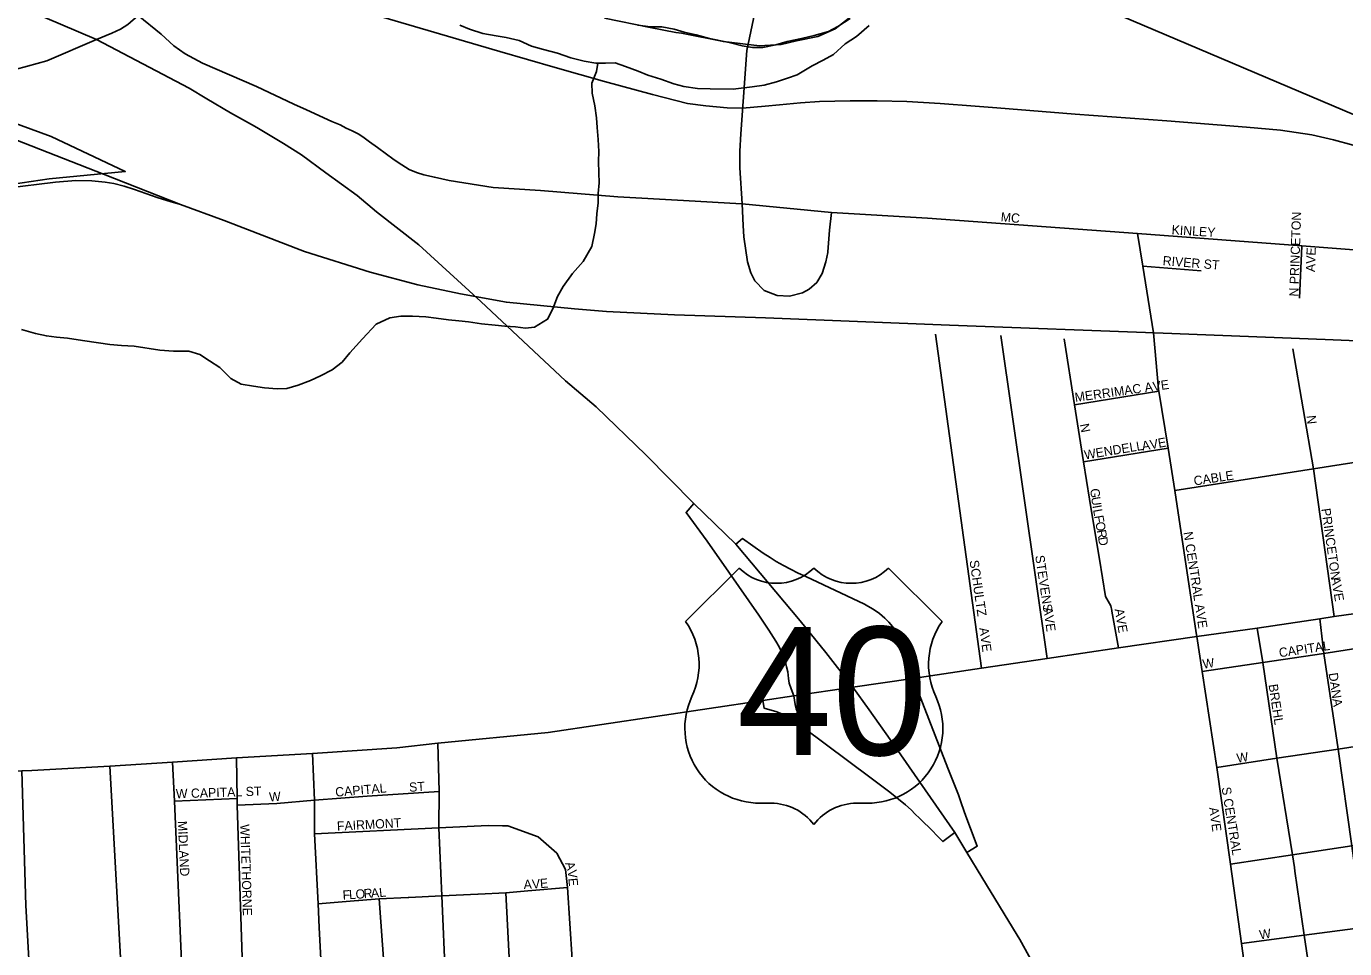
# Model space of a CAD drawing. Extents: x 0 to 34, y -6.2 to 22.
# Drawn here: x 3.469 to 4.825, y 17.432 to 18.38 of the extents above; entities that cross this region are included whole.
import ezdxf

# ---------------------------------------------------------------- set-up
doc = ezdxf.new("R2010")
doc.units = 0
for name, color, linetype in [('GM_X_City_Street', 7, 'Continuous'), ('GM_X_City_Street_Text', 7, 'Continuous'), ('GM_X_Corporation', 7, 'Continuous'), ('GM_X_Interchange_Ramps', 7, 'Continuous'), ('GM_X_Interstate_Route', 7, 'Continuous'), ('GM_X_Major_River', 7, 'Continuous'), ('GM_X_Minor_River', 7, 'Continuous'), ('GM_X_Rail_Line', 7, 'Continuous'), ('GM_X_Section', 7, 'Continuous'), ('GM_X_US_Route', 7, 'Continuous'), ('GM_X_US_Shield', 7, 'Continuous')]:
    doc.layers.add(name, color=color, linetype=linetype)

msp = doc.modelspace()

# ---------------------------------------------------------------- linework, layer by layer
at = {"layer": 'GM_X_City_Street'}
for points in [[(4.2061, 18.1755), (4.2049, 18.1978), (4.2028, 18.2345), (4.2028, 18.2519), (4.2036, 18.2695), (4.2061, 18.303), (4.2099, 18.3554), (4.2236, 18.4209)], [(3.354, 18.3169), (3.357, 18.3181), (3.3663, 18.322), (3.3881, 18.3285), (3.3978, 18.3304), (3.415, 18.3325), (3.4446, 18.3339), (3.4576, 18.3358), (3.4701, 18.3392), (3.4899, 18.3448), (3.5412, 18.3666), (3.5569, 18.373), (3.5657, 18.3772), (3.5734, 18.3821), (3.5839, 18.3913)], [(4.1446, 18.2012), (4.0771, 18.205), (3.9976, 18.2114), (3.949, 18.2146), (3.9038, 18.2216), (3.8886, 18.2249), (3.8777, 18.2273), (3.8702, 18.2297), (3.8627, 18.2328), (3.8512, 18.24), (3.8457, 18.2439), (3.8392, 18.2488), (3.83, 18.2556), (3.8219, 18.2614), (3.8163, 18.2656), (3.8108, 18.2691), (3.8041, 18.2728), (3.798, 18.2756), (3.7916, 18.2788), (3.7831, 18.2824), (3.7569, 18.2944), (3.7442, 18.3002), (3.7056, 18.3184), (3.65, 18.3421), (3.6324, 18.352), (3.6207, 18.3601), (3.6075, 18.3721), (3.5839, 18.3913)], [(4.2043, 18.1978), (4.1446, 18.2012)], [(4.6114, 18.1673), (4.3955, 18.183), (4.297, 18.1886), (4.2049, 18.1978), (4.2043, 18.1978)], [(4.297, 18.1886), (4.295, 18.1706), (4.2931, 18.1484), (4.293, 18.1476)], [(4.293, 18.1476), (4.291, 18.1379), (4.2873, 18.1259), (4.2819, 18.1168), (4.2739, 18.1099), (4.267, 18.1063), (4.2536, 18.1026), (4.2409, 18.1034), (4.2278, 18.1085), (4.218, 18.1186), (4.214, 18.1266), (4.2107, 18.1379), (4.2067, 18.1637), (4.2061, 18.1755)], [(5.0508, 18.1356), (4.9707, 18.141), (4.8473, 18.1492), (4.7807, 18.1543), (4.6114, 18.1673)], [(4.6719, 17.7566), (4.65, 17.903), (4.643, 17.9465), (4.6336, 18.0049), (4.6332, 18.0072), (4.6279, 18.065), (4.6169, 18.1336), (4.6114, 18.1673)], [(4.7782, 18.1007), (4.7807, 18.1543)], [(4.6169, 18.1336), (4.6769, 18.1289)], [(4.451, 17.7202), (4.4038, 18.0638)], [(4.5186, 17.7302), (4.4712, 18.0622)], [(4.5623, 17.8941), (4.5562, 17.9324), (4.5469, 17.9911), (4.5362, 18.0587)], [(4.8138, 17.7733), (4.7925, 17.9253), (4.7712, 18.0484)], [(4.5469, 17.9911), (4.6336, 18.0049)], [(4.65, 17.903), (4.7925, 17.9253), (4.8603, 17.9359), (4.9313, 17.9469), (4.9831, 17.955)], [(4.5562, 17.9324), (4.643, 17.9465)], [(4.5852, 17.7796), (4.5843, 17.7845), (4.5785, 17.7938), (4.5726, 17.8323), (4.563, 17.8896), (4.5623, 17.8941)], [(4.5919, 17.741), (4.5853, 17.7789), (4.5852, 17.7796)], [(4.7734, 17.5116), (4.7729, 17.5155), (4.771, 17.5283), (4.755, 17.6276), (4.7405, 17.726), (4.7347, 17.7615)], [(4.7405, 17.726), (4.8033, 17.7355), (4.8626, 17.7445), (4.9332, 17.7556), (5.0048, 17.7658)], [(4.8832, 17.1912), (4.8743, 17.2504), (4.87, 17.2759), (4.8718, 17.281), (4.8638, 17.3316), (4.8432, 17.4538), (4.8319, 17.5375), (4.818, 17.6371), (4.8033, 17.7355), (4.7989, 17.7709)], [(4.7071, 17.5186), (4.6931, 17.6183), (4.6782, 17.7168), (4.6725, 17.7528), (4.6719, 17.7566)], [(4.6782, 17.7168), (4.7405, 17.726)], [(4.6931, 17.6183), (4.755, 17.6276), (4.818, 17.6371), (4.8773, 17.6461), (4.9579, 17.6581), (5.0194, 17.6672), (5.0489, 17.6714)], [(3.9039, 17.3122), (3.8963, 17.4862), (3.8933, 17.5562), (3.8934, 17.5933), (3.8922, 17.643)], [(3.6529, 16.9916), (3.642, 17.14), (3.6314, 17.3561), (3.6214, 17.5837), (3.6194, 17.6236)], [(3.7167, 17.0066), (3.7063, 17.1432), (3.6931, 17.3603), (3.6859, 17.5795), (3.6856, 17.5864), (3.685, 17.6282)], [(3.7947, 17.0334), (3.7927, 17.0589), (3.7792, 17.2778), (3.7702, 17.4538), (3.769, 17.4781), (3.7653, 17.55), (3.7653, 17.5845), (3.7633, 17.6324)], [(3.5038, 16.9353), (3.5023, 16.9435), (3.5002, 16.955), (3.4976, 16.9872), (3.494, 17.0525), (3.4904, 17.0753), (3.4856, 17.1654), (3.4855, 17.1663), (3.4847, 17.1818), (3.4743, 17.3716), (3.4685, 17.4762), (3.4642, 17.6146)], [(3.5896, 16.9856), (3.5877, 17.0084), (3.582, 17.0834), (3.579, 17.137), (3.5767, 17.1883), (3.5694, 17.352), (3.5682, 17.3797), (3.5549, 17.6194)], [(3.6214, 17.5837), (3.6856, 17.5864)], [(3.6859, 17.5795), (3.7265, 17.5812), (3.7653, 17.5845)], [(3.7653, 17.5845), (3.8194, 17.5886), (3.8934, 17.5933)], [(3.7653, 17.55), (3.8933, 17.5562), (3.9437, 17.5586), (3.9587, 17.5582)], [(3.9587, 17.5582), (3.9591, 17.5582), (3.9642, 17.5581), (3.9954, 17.547), (4.0144, 17.5302), (4.0235, 17.5133), (4.0253, 17.4946)], [(4.8139, 17.2406), (4.813, 17.2463), (4.8098, 17.2662), (4.783, 17.4459), (4.7734, 17.5116)], [(3.8623, 17.4845), (3.8963, 17.4862), (3.9334, 17.488), (3.9337, 17.488)], [(3.9337, 17.488), (3.9621, 17.4893), (3.9846, 17.4912), (3.9846, 17.4912)], [(3.9911, 17.072), (3.9704, 17.3297), (3.9621, 17.4893)], [(3.9846, 17.4912), (4.0253, 17.4946)], [(4.035, 17.3455), (4.0349, 17.3466), (4.0253, 17.4946)], [(3.769, 17.4781), (3.8101, 17.4813), (3.8108, 17.4814)], [(3.8108, 17.4814), (3.8317, 17.483), (3.8615, 17.4845), (3.8623, 17.4845)], [(3.845, 17.2987), (3.8317, 17.483)], [(4.7185, 17.4373), (4.783, 17.4459), (4.8432, 17.4538), (4.9032, 17.4617), (4.9884, 17.473), (5.0459, 17.4806), (5.0754, 17.4845)]]:
    msp.add_lwpolyline(points, dxfattribs=at)
at = {"layer": 'GM_X_Corporation'}
msp.add_lwpolyline([(3.4223, 18.2933), (3.4945, 18.2667), (3.5707, 18.2308), (3.4925, 18.2234), (3.4367, 18.2152)], dxfattribs=at)
at = {"layer": 'GM_X_Interchange_Ramps'}
for points in [[(4.1555, 17.8896), (4.1473, 17.8803), (4.1689, 17.8507), (4.1912, 17.819), (4.2222, 17.7748), (4.2325, 17.7595), (4.2396, 17.7481), (4.2431, 17.7422), (4.2455, 17.7372), (4.2479, 17.7314), (4.2495, 17.7266), (4.2508, 17.7218), (4.2519, 17.7164), (4.2526, 17.7095), (4.2533, 17.7047), (4.2556, 17.6991), (4.2583, 17.6917)], [(4.3806, 17.7098), (4.3776, 17.7187), (4.3761, 17.7284), (4.3752, 17.7324), (4.3736, 17.7376), (4.3717, 17.7427), (4.3696, 17.7475), (4.3666, 17.7529), (4.3635, 17.7579), (4.3597, 17.7631), (4.3559, 17.7674), (4.3516, 17.7717), (4.3463, 17.7763), (4.3398, 17.781), (4.3344, 17.7841), (4.3308, 17.786), (4.2704, 17.8145), (4.2626, 17.818), (4.2546, 17.8219), (4.2474, 17.8258), (4.24, 17.8301), (4.2337, 17.8339), (4.2265, 17.8386), (4.2053, 17.8535), (4.1985, 17.8479)], [(4.4361, 17.5308), (4.4468, 17.5371), (4.44, 17.5554), (4.4352, 17.5682), (4.4307, 17.5808), (4.4274, 17.5901), (4.4166, 17.6175), (4.3838, 17.7013), (4.3806, 17.7098)], [(4.2583, 17.6917), (4.2596, 17.6828), (4.2607, 17.6783), (4.2625, 17.6738), (4.2645, 17.6699), (4.2665, 17.6669), (4.2698, 17.6628), (4.2674, 17.6596)], [(4.2264, 17.687), (4.2276, 17.6792), (4.2408, 17.6753), (4.2464, 17.6731), (4.2513, 17.6708), (4.2569, 17.6675), (4.2619, 17.664), (4.2674, 17.6596), (4.3377, 17.6072), (4.3568, 17.5927), (4.373, 17.5799), (4.3787, 17.5745), (4.3831, 17.5703), (4.3873, 17.5662), (4.3922, 17.5614), (4.3969, 17.5568), (4.4011, 17.5526), (4.405, 17.5486), (4.4115, 17.542), (4.4237, 17.5512)]]:
    msp.add_lwpolyline(points, dxfattribs=at)
at = {"layer": 'GM_X_Interstate_Route'}
for points in [[(4.3418, 18.4877), (4.3545, 18.4838), (4.4533, 18.4494), (4.4812, 18.4384), (4.5209, 18.4223), (4.5477, 18.4108), (4.571, 18.4007), (4.8701, 18.274), (4.9358, 18.2459), (4.9591, 18.2362), (4.9768, 18.2297), (5.0011, 18.2219), (5.0179, 18.2177), (5.0369, 18.2146), (5.0555, 18.2123), (5.0721, 18.2113), (5.0956, 18.2113), (5.1163, 18.2131), (5.13, 18.2148), (5.1436, 18.2173), (5.1588, 18.2209), (5.1693, 18.2235), (5.1842, 18.2285)], [(3.4695, 18.3971), (3.5412, 18.3666), (3.6364, 18.3165), (3.6546, 18.3056)], [(3.6546, 18.3056), (3.6788, 18.2912), (3.7005, 18.2793), (3.7061, 18.276)], [(3.7061, 18.276), (3.7335, 18.2596), (3.7519, 18.2481), (3.7771, 18.2296), (3.8091, 18.2063), (3.8292, 18.1893), (3.8724, 18.1554), (3.9364, 18.0973), (4.0235, 18.0157), (4.055, 17.989), (4.1061, 17.9397), (4.1555, 17.8896), (4.1985, 17.8479), (4.2647, 17.7691), (4.2912, 17.7365), (4.3189, 17.7008)], [(4.3189, 17.7008), (4.3357, 17.6773)], [(4.3357, 17.6773), (4.3572, 17.647), (4.4237, 17.5512), (4.4361, 17.5308), (4.4516, 17.5053)], [(4.4516, 17.5053), (4.4877, 17.4458)], [(4.4877, 17.4458), (4.4905, 17.4412), (4.582, 17.2751), (4.5996, 17.2443), (4.6144, 17.2203)]]:
    msp.add_lwpolyline(points, dxfattribs=at)
at = {"layer": 'GM_X_Major_River'}
for points in [[(4.3162, 18.3883), (4.3033, 18.38), (4.2938, 18.3747), (4.279, 18.3706), (4.2661, 18.3677), (4.2513, 18.3644), (4.2396, 18.361), (4.2263, 18.3584), (4.2157, 18.3585), (4.2051, 18.3601), (4.1918, 18.3636), (4.1714, 18.3675), (4.1578, 18.3714), (4.1453, 18.3741), (4.1351, 18.3772), (4.1226, 18.3795), (4.1109, 18.3796), (4.0976, 18.3812)], [(3.9146, 18.3812), (3.9245, 18.3773), (3.9384, 18.3727), (3.9521, 18.3703), (3.9623, 18.3687), (3.9759, 18.3656), (3.9884, 18.3599), (4.0009, 18.3564), (4.0152, 18.3525), (4.0288, 18.3479), (4.0425, 18.3444), (4.0546, 18.3424), (4.0644, 18.3423), (4.0743, 18.3426), (4.0852, 18.3388), (4.0981, 18.3342), (4.1079, 18.3299), (4.1215, 18.3257), (4.1348, 18.321), (4.145, 18.3183), (4.159, 18.3163), (4.1722, 18.3159), (4.1957, 18.3157), (4.2154, 18.3179), (4.2276, 18.3197), (4.2405, 18.3231), (4.2515, 18.3268), (4.2617, 18.3301), (4.2769, 18.3395), (4.2883, 18.3455), (4.299, 18.3512), (4.3108, 18.3621), (4.3226, 18.3696), (4.3355, 18.3809)]]:
    msp.add_lwpolyline(points, dxfattribs=at)
at = {"layer": 'GM_X_Minor_River'}
msp.add_lwpolyline([(4.0566, 18.3424), (4.0554, 18.3338), (4.0503, 18.3217), (4.0509, 18.3115), (4.0534, 18.2985), (4.0551, 18.286), (4.0561, 18.2761), (4.0571, 18.2639), (4.0577, 18.2514), (4.0572, 18.2412), (4.0578, 18.2294), (4.058, 18.2191), (4.0571, 18.2081), (4.057, 18.1986), (4.0557, 18.1873), (4.0548, 18.177), (4.0531, 18.1672), (4.0503, 18.1539), (4.0417, 18.1385), (4.0306, 18.1261), (4.0209, 18.1126), (4.0151, 18.1024), (4.0104, 18.0896), (4.0049, 18.079), (3.9916, 18.0708), (3.9821, 18.0698), (3.9718, 18.0711), (3.9609, 18.072), (3.951, 18.0729), (3.937, 18.0742), (3.9238, 18.0763), (3.9136, 18.0772), (3.903, 18.0785), (3.8905, 18.0802), (3.8799, 18.0815), (3.8659, 18.082), (3.8541, 18.0822), (3.8427, 18.0805), (3.8286, 18.0738), (3.8148, 18.0588), (3.8017, 18.0446), (3.7936, 18.0348), (3.7833, 18.027), (3.7714, 18.0207), (3.7611, 18.0159), (3.7486, 18.0111), (3.7368, 18.0079), (3.7269, 18.0073), (3.7137, 18.0086), (3.7027, 18.0102), (3.6898, 18.0123), (3.6793, 18.0182), (3.6681, 18.0293), (3.6572, 18.0363), (3.6474, 18.0429), (3.6361, 18.0461), (3.6202, 18.0463), (3.6062, 18.0473), (3.5797, 18.0514), (3.5668, 18.052), (3.5547, 18.0529), (3.543, 18.0546), (3.5267, 18.0571), (3.5112, 18.0596), (3.4999, 18.0605), (3.4896, 18.0618), (3.4783, 18.0642), (3.464, 18.0686)], dxfattribs=at)
at = {"layer": 'GM_X_Rail_Line'}
for points in [[(3.8224, 18.3932), (3.9335, 18.3607), (3.9558, 18.3541), (4.0127, 18.3379), (4.0635, 18.3234), (4.1129, 18.3099), (4.1487, 18.3009), (4.1676, 18.2983), (4.1897, 18.2963), (4.2054, 18.2961), (4.2286, 18.2981)], [(2.2755, 18.3366), (2.399, 18.3449), (2.4759, 18.3502), (2.5318, 18.3539), (2.5883, 18.3579), (2.6939, 18.365), (2.8339, 18.3746), (2.8626, 18.3756), (2.9558, 18.3774), (3.0038, 18.3761), (3.0567, 18.3729), (3.1054, 18.3674), (3.1208, 18.3653), (3.1653, 18.3574), (3.1923, 18.3522), (3.2369, 18.3415), (3.279, 18.3296), (3.3073, 18.3207), (3.3671, 18.2986), (3.458, 18.2633), (3.5483, 18.2281)], [(4.2286, 18.2981), (4.2436, 18.2993), (4.265, 18.3016), (4.2846, 18.3027), (4.3162, 18.3035), (4.3437, 18.3037), (4.3745, 18.3028), (4.4087, 18.3007), (4.4447, 18.298), (4.4668, 18.2965), (4.5473, 18.29), (4.6418, 18.2829), (4.7237, 18.2765), (4.7586, 18.2733), (4.7907, 18.2686), (4.8131, 18.2633), (4.8334, 18.2579), (4.8511, 18.2521), (4.9336, 18.2204), (4.9803, 18.2024), (5.0081, 18.1943)], [(3.4147, 18.2097), (3.4988, 18.2198), (3.5198, 18.2216), (3.5364, 18.2213), (3.55, 18.22), (3.5588, 18.2184), (3.5695, 18.2158), (3.5801, 18.2125), (3.6034, 18.2042), (3.6178, 18.1997), (3.6274, 18.197)], [(3.5483, 18.2281), (3.6274, 18.197)], [(3.6274, 18.197), (3.6725, 18.1806), (3.7549, 18.1486), (3.8224, 18.1273), (3.8715, 18.1143), (3.9153, 18.1052), (3.9626, 18.0965), (4.0328, 18.0896), (4.0656, 18.0871), (4.1355, 18.0835), (4.2291, 18.0803), (4.4181, 18.073), (4.6379, 18.0646), (4.8046, 18.0581), (4.9693, 18.0513), (5.0439, 18.0491)]]:
    msp.add_lwpolyline(points, dxfattribs=at)
at = {"layer": 'GM_X_Section'}
msp.add_lwpolyline([(4.319, 18.3917), (4.3007, 18.3774), (4.2828, 18.3696), (4.2608, 18.3652), (4.2453, 18.3615), (4.2229, 18.3601), (4.1858, 18.3645), (4.1427, 18.3731), (4.137, 18.3739), (4.1105, 18.379), (4.0636, 18.3884)], dxfattribs=at)
at = {"layer": 'GM_X_US_Route'}
for points in [[(4.3806, 17.7098), (4.451, 17.7202), (4.5186, 17.7302), (4.5919, 17.741), (4.6725, 17.7528), (4.7347, 17.7615), (4.7989, 17.7709), (4.8138, 17.7733), (4.8583, 17.7796), (4.8845, 17.7839), (4.9279, 17.7904), (4.9528, 17.794), (4.9999, 17.8014), (5.0071, 17.8027), (5.0833, 17.8136), (5.1436, 17.8226), (5.1732, 17.8269)], [(4.3189, 17.7008), (4.3806, 17.7098)], [(4.2264, 17.687), (4.2264, 17.687), (4.2583, 17.6917), (4.3189, 17.7008)], [(3.4746, 17.6152), (3.5549, 17.6194), (3.6194, 17.6236), (3.685, 17.6282), (3.7633, 17.6324), (3.8498, 17.6382), (3.8922, 17.643), (4.0054, 17.654), (4.2264, 17.687)], [(2.7722, 17.5767), (2.835, 17.5781), (2.8913, 17.5814), (2.8978, 17.5817), (2.9479, 17.586), (2.9633, 17.5869), (3.0204, 17.5901), (3.0294, 17.5906), (3.0594, 17.5911), (3.0843, 17.5926), (3.1, 17.5935), (3.1552, 17.598), (3.1748, 17.5984), (3.2207, 17.6008), (3.2401, 17.602), (3.2786, 17.6048), (3.3066, 17.6072), (3.3458, 17.608), (3.36, 17.6082), (3.4047, 17.6118), (3.4151, 17.6124), (3.4642, 17.6146), (3.4746, 17.6152)], [(4.7071, 17.5186), (4.771, 17.5283), (4.8319, 17.5375), (4.8908, 17.5464), (4.9758, 17.5594), (5.0334, 17.5681), (5.1152, 17.5805)], [(4.7722, 17.089), (4.7612, 17.1636), (4.7485, 17.2517), (4.7342, 17.3247), (4.7258, 17.3847), (4.7185, 17.4373), (4.7071, 17.5186)]]:
    msp.add_lwpolyline(points, dxfattribs=at)
at = {"layer": 'GM_X_US_Shield'}
for p, q in [((4.2018, 17.8232), (4.1469, 17.7682)), ((4.4106, 17.7682), (4.3556, 17.8232)), ((4.2238, 17.5815), (4.2348, 17.5815)), ((4.3227, 17.5815), (4.3337, 17.5815))]:
    msp.add_line(p, q, dxfattribs=at)
for centre, radius, start, end in [((4.2403, 17.8624), 0.0549, 225.573, 314.427), ((4.3172, 17.8624), 0.0549, 225.573, 314.427), ((4.0839, 17.7241), 0.0769, 334.5471, 35.0009), ((4.4736, 17.7241), 0.0769, 144.9991, 205.4529), ((4.223, 17.6584), 0.0769, 154.8319, 270.6383), ((4.3345, 17.6584), 0.0769, 269.3617, 25.1681), ((4.2348, 17.5265), 0.0549, 36.8699, 90), ((4.3227, 17.5265), 0.0549, 90, 143.1301)]:
    msp.add_arc(centre, radius, start, end, dxfattribs=at)

# ---------------------------------------------------------------- texts
at = {"layer": 'GM_X_City_Street_Text'}
for s, rotation, p in [('MC', 354.8083, (4.4706, 18.1797)), ('N PRINCETON', 88.0895, (4.777, 18.1022)), ('KINLEY', 356.3071, (4.6464, 18.1664)), ('AVE', 88.0186, (4.7941, 18.1274)), ('RIVER ST', 355.3132, (4.6372, 18.1347)), ('MERRIMAC AVE', 7.9796, (4.5477, 17.9939)), ('N', 275.7084, (4.7855, 17.9798)), ('N', 281.3057, (4.5522, 17.9708)), ('WENDELL', 9.4634, (4.5576, 17.9347)), ('AVE', 9.7774, (4.6168, 17.9439)), ('CABLE', 8.6529, (4.6701, 17.908)), ('G', 274.8145, (4.563, 17.9047)), ('U', 278.4316, (4.5638, 17.8958)), ('I', 280.0994, (4.5651, 17.8872)), ('L', 280.1465, (4.5658, 17.8831)), ('PRINCETON', 278.1285, (4.8005, 17.884)), ('F', 280.1714, (4.567, 17.8766)), ('O', 280.1524, (4.5682, 17.87)), ('R', 280.1568, (4.5696, 17.8618)), ('D', 280.1537, (4.5709, 17.8544)), ('N CENTRAL AVE', 278.8659, (4.6588, 17.8599)), ('SCHULTZ', 278.2584, (4.4388, 17.8307)), ('STEVENS', 278.5295, (4.5063, 17.8357)), ('AVE', 279.7847, (4.8105, 17.8133)), ('AVE', 277.8566, (4.5147, 17.7824)), ('AVE', 279.7834, (4.588, 17.7808)), ('AVE', 277.8566, (4.4488, 17.7615)), ('CAPITAL', 8.3649, (4.7577, 17.7314)), ('W', 8.7411, (4.6793, 17.7197)), ('DANA', 278.5313, (4.808, 17.7149)), ('BREHL', 278.653, (4.7463, 17.7032)), ('W', 8.7411, (4.7143, 17.623)), ('W CAPITAL ST', 1.8078, (3.6229, 17.5864)), ('CAPITAL', 4.8438, (3.787, 17.5881)), ('ST', 3.5746, (3.8628, 17.5931)), ('S CENTRAL', 279.2117, (4.698, 17.5974)), ('W', 3.9539, (3.7189, 17.5831)), ('AVE', 277.8492, (4.6852, 17.5768)), ('MIDLAND', 272.6012, (3.6247, 17.563)), ('WHITETHORNE', 271.7005, (3.6889, 17.5597)), ('FAIRMONT', 3.1375, (3.7886, 17.5531)), ('A', 288.0894, (4.0228, 17.5197)), ('A', 2.5797, (3.9805, 17.4931)), ('V', 4.4163, (3.9892, 17.4935)), ('E', 4.5939, (3.9975, 17.4941)), ('V', 277.3636, (4.0253, 17.5122)), ('E', 275.1969, (4.0263, 17.5041)), ('F', 3.8286, (3.7945, 17.4822)), ('L', 3.8304, (3.8011, 17.4827)), ('O', 3.8294, (3.8078, 17.4831)), ('R', 3.8293, (3.8161, 17.4837)), ('A', 4.2024, (3.8236, 17.4842)), ('L', 5.9081, (3.8322, 17.4848)), ('W', 8.7411, (4.7376, 17.4414))]:
    msp.add_text(s, height=0.00947, rotation=rotation, dxfattribs=at).set_placement(p)
at = {"layer": 'GM_X_US_Shield'}
msp.add_text('40', height=0.13184, dxfattribs=at).set_placement((4.1995, 17.6309))

doc.saveas('drawing.dxf')
